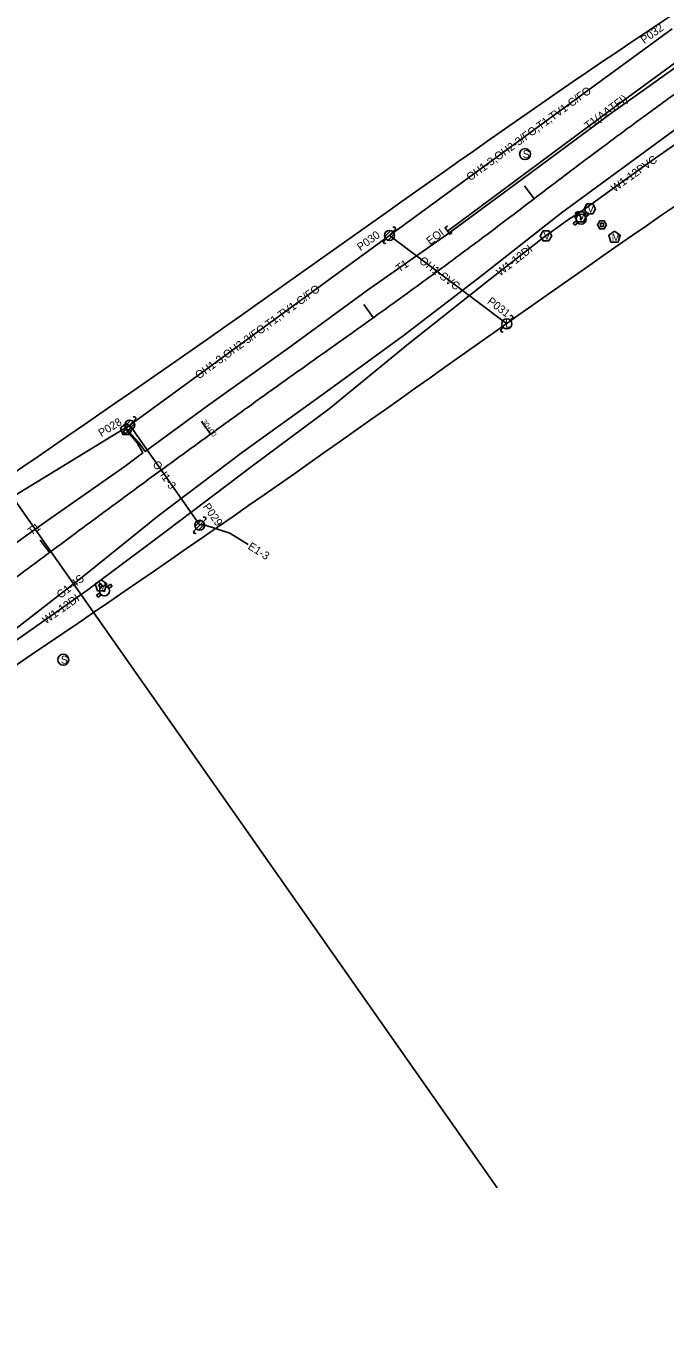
# Model space of a CAD drawing. Extents: x 1991878 to 2008544, y 770238 to 1141211.
# Drawn here: x 2005456 to 2005776, y 1139564 to 1140212 of the extents above; entities that cross this region are included whole.
import ezdxf

# ---------------------------------------------------------------- set-up
doc = ezdxf.new("R2010")
doc.units = 0
for name, color, linetype in [('RD_EX_SU_Elec', 7, 'Continuous'), ('RD_EX_SU_Gas', 7, 'Continuous'), ('RD_EX_SU_H2O', 7, 'Continuous'), ('RD_EX_SU_Ovhd', 7, 'Continuous'), ('RD_EX_SU_Pole', 7, 'Continuous'), ('RD_EX_SU_Sewer', 7, 'Continuous'), ('RD_EX_SU_SwpLmt', 7, 'Continuous'), ('RD_EX_SU_Telecom', 7, 'Continuous'), ('RD_EX_SU_TX_Elec', 7, 'Continuous'), ('RD_EX_SU_TX_Gas', 7, 'Continuous'), ('RD_EX_SU_TX_H2O', 7, 'Continuous'), ('RD_EX_SU_TX_Ovhd', 7, 'Continuous'), ('RD_EX_SU_TX_Pole', 7, 'Continuous'), ('RD_EX_SU_TX_Telecom', 7, 'Continuous'), ('RD_HC_Cl', 7, 'Continuous')]:
    doc.layers.add(name, color=color, linetype=linetype)

msp = doc.modelspace()

# ---------------------------------------------------------------- linework, layer by layer
at = {"layer": 'RD_EX_SU_Elec'}
msp.add_lwpolyline([(2005542.87, 1139962.08), (2005544.55, 1139962.45), (2005557.92, 1139958.21), (2005567.13, 1139952.46)], dxfattribs=at)
at = {"layer": 'RD_EX_SU_Gas'}
msp.add_lwpolyline([(2005803.2, 1140176.39), (2005763.13, 1140146.95), (2005723.81, 1140118.19), (2005683.92, 1140086.83), (2005644.62, 1140056.74), (2005604.18, 1140027.33), (2005564.31, 1139998.64), (2005521.91, 1139966.72), (2005504.56, 1139952.57), (2005484.04, 1139936.17), (2005443.65, 1139904.67), (2005433.24, 1139897.21), (2005404.27, 1139876.33), (2005364.62, 1139848.8), (2005341.03, 1139829.73), (2005334.6, 1139822.82), (2005321.62, 1139805.66), (2005312.49, 1139784.03), (2005307.05, 1139765.3), (2005297.89, 1139715.34), (2005290.82, 1139666.35), (2005285.78, 1139616.8), (2005285.17, 1139566.36), (2005290.52, 1139518.04)], dxfattribs=at)
at = {"layer": 'RD_EX_SU_H2O'}
for p, q in [((2005731.72, 1140118.73), (2005730.71, 1140117.98)), ((2005730.71, 1140117.98), (2005731.67, 1140116.69)), ((2005732.7, 1140117.42), (2005731.72, 1140118.73)), ((2005736.73, 1140118.3), (2005735.1, 1140117.09)), ((2005737.48, 1140117.29), (2005736.73, 1140118.3)), ((2005731.23, 1140114.21), (2005729.65, 1140113.04)), ((2005729.65, 1140113.04), (2005730.41, 1140112.03)), ((2005730.41, 1140112.03), (2005731.94, 1140113.17)), ((2005735.89, 1140116.11), (2005737.48, 1140117.29)), ((2005493.23, 1139932.93), (2005492.24, 1139932.15)), ((2005492.24, 1139932.15), (2005493.24, 1139930.89)), ((2005494.25, 1139931.65), (2005493.23, 1139932.93)), ((2005498.25, 1139932.65), (2005496.66, 1139931.39)), ((2005497.48, 1139930.43), (2005499.03, 1139931.66)), ((2005499.03, 1139931.66), (2005498.25, 1139932.65)), ((2005492.87, 1139928.4), (2005491.34, 1139927.18)), ((2005491.34, 1139927.18), (2005492.12, 1139926.19)), ((2005492.12, 1139926.19), (2005493.62, 1139927.38))]:
    msp.add_line(p, q, dxfattribs=at)
for points in [[(2005807.57, 1140171.15), (2005766.02, 1140142.13), (2005735.93, 1140120.52), (2005732.28, 1140118.09), (2005726.84, 1140114.53), (2005714.88, 1140105.91), (2005686.65, 1140083.86), (2005647.25, 1140052.78), (2005607.69, 1140020.33), (2005569.36, 1139991.81), (2005526.81, 1139959.7), (2005492.34, 1139933.84), (2005487.01, 1139929.87), (2005446.84, 1139901.54), (2005435.17, 1139892.92), (2005426.67, 1139902.32), (2005412.65, 1139920.51), (2005407.97, 1139926.34)], [(2005733.6, 1140115.07), (2005733.62, 1140115.73), (2005732.63, 1140117.39), (2005732.2, 1140118.04)]]:
    msp.add_lwpolyline(points, dxfattribs=at)
for points in [[(2005736.21, 1140116.26), (2005734.76, 1140118.76), (2005731.88, 1140118.76), (2005730.43, 1140116.26), (2005731.88, 1140113.76), (2005734.76, 1140113.76)], [(2005740.85, 1140120.22), (2005739.41, 1140122.72), (2005736.52, 1140122.72), (2005735.08, 1140120.22), (2005736.52, 1140117.72), (2005739.41, 1140117.72)], [(2005718.91, 1140106.7), (2005717.46, 1140109.2), (2005714.58, 1140109.2), (2005713.13, 1140106.7), (2005714.58, 1140104.2), (2005717.46, 1140104.2)], [(2005750.31, 1140109.11), (2005747.41, 1140107), (2005748.52, 1140103.59), (2005752.11, 1140103.59), (2005753.21, 1140107)], [(2005493.56, 1139934.88), (2005490.65, 1139932.77), (2005491.76, 1139929.36), (2005495.35, 1139929.36), (2005496.46, 1139932.77)]]:
    msp.add_lwpolyline(points, close=True, dxfattribs=at)
for centre, radius in [((2005733.6, 1140115.07), 2.52), ((2005733.6, 1140115.07), 0.315), ((2005495.21, 1139929.33), 2.52), ((2005495.21, 1139929.33), 0.315)]:
    msp.add_circle(centre, radius, dxfattribs=at)
for centre, start, end in [((2005733.6, 1140115.07), 200.01842, 228.99474), ((2005733.6, 1140115.07), 110.92525, 139.89248), ((2005733.6, 1140115.07), 24.36471, 53.34102), ((2005495.21, 1139929.33), 112.61376, 141.581), ((2005495.21, 1139929.33), 26.05322, 55.02954), ((2005495.21, 1139929.33), 201.70694, 230.68325)]:
    msp.add_arc(centre, 2.52, start, end, dxfattribs=at)
at = {"layer": 'RD_EX_SU_Ovhd'}
for p, q in [((2005637.78, 1140106.93), (2005779.22, 1140210.16)), ((2005507.86, 1140012.14), (2005637.78, 1140106.93)), ((2005637.78, 1140106.93), (2005696.44, 1140062.74)), ((2005325.23, 1139900.3), (2005507.86, 1140012.14)), ((2005542.87, 1139962.08), (2005507.86, 1140012.14))]:
    msp.add_line(p, q, dxfattribs=at)
at = {"layer": 'RD_EX_SU_Pole'}
for p, q in [((2005634.95, 1140104.1), (2005636.01, 1140105.16)), ((2005635.36, 1140106.28), (2005638.42, 1140109.35)), ((2005636.01, 1140105.16), (2005639.54, 1140108.7)), ((2005637.13, 1140104.52), (2005640.19, 1140107.58)), ((2005639.54, 1140108.7), (2005640.6, 1140109.76)), ((2005693.61, 1140059.91), (2005694.67, 1140060.97)), ((2005698.21, 1140064.51), (2005699.27, 1140065.57)), ((2005505.44, 1140011.49), (2005508.5, 1140014.55)), ((2005506.09, 1140010.37), (2005509.62, 1140013.9)), ((2005509.62, 1140013.9), (2005510.68, 1140014.96)), ((2005505.03, 1140009.31), (2005506.09, 1140010.37)), ((2005507.21, 1140009.72), (2005510.27, 1140012.78)), ((2005540.45, 1139961.43), (2005543.52, 1139964.49)), ((2005541.1, 1139960.31), (2005544.64, 1139963.84)), ((2005542.22, 1139959.66), (2005545.28, 1139962.72)), ((2005544.64, 1139963.84), (2005545.7, 1139964.9)), ((2005540.04, 1139959.25), (2005541.1, 1139960.31))]:
    msp.add_line(p, q, dxfattribs=at)
for centre in [(2005637.78, 1140106.93), (2005696.44, 1140062.74), (2005507.86, 1140012.14), (2005542.87, 1139962.08)]:
    msp.add_circle(centre, 2.5, dxfattribs=at)
for centre, start, end in [((2005640.07, 1140110.29), 315.01158, 135.01158), ((2005635.48, 1140103.57), 135.01158, 315.01158), ((2005698.74, 1140066.1), 315.01158, 135.01158), ((2005694.14, 1140059.38), 135.01158, 315.01158), ((2005510.15, 1140015.5), 315.01158, 135.01158), ((2005505.56, 1140008.78), 135.01158, 315.01158), ((2005545.17, 1139965.44), 315.01158, 135.01158), ((2005540.57, 1139958.72), 135.01158, 315.01158)]:
    msp.add_arc(centre, 0.75, start, end, dxfattribs=at)
at = {"layer": 'RD_EX_SU_Sewer'}
for points in [[(2005746.37, 1140112.21), (2005745.21, 1140114.21), (2005742.91, 1140114.21), (2005741.75, 1140112.21), (2005742.91, 1140110.21), (2005745.21, 1140110.21)], [(2005744.88, 1140113.02), (2005743.24, 1140113.02), (2005743.24, 1140111.39), (2005744.88, 1140111.39)]]:
    msp.add_lwpolyline(points, close=True, dxfattribs=at)
for centre in [(2005705.61, 1140147.54), (2005474.63, 1139894.92)]:
    msp.add_circle(centre, 2.75, dxfattribs=at)
at = {"layer": 'RD_EX_SU_SwpLmt'}
for points in [[(2005347.6, 1139821.95), (2005413.49, 1139866.73), (2005588.16, 1139984.08), (2005817.83, 1140151.69), (2006031.43, 1140278.81), (2006110.28, 1140318.03), (2006387.29, 1140416.7), (2006495.91, 1140463.06), (2006601.39, 1140518.44), (2006718.46, 1140585.62), (2006783.57, 1140627.26), (2006823.57, 1140659.06)], [(2005347.6, 1139821.95), (2005413.49, 1139866.73), (2005588.16, 1139984.08), (2005817.83, 1140151.69), (2006031.43, 1140278.81), (2006110.28, 1140318.03), (2006387.29, 1140416.7), (2006495.91, 1140463.06), (2006601.39, 1140518.44), (2006706.19, 1140578.58), (2006762.55, 1140613.92), (2006787.85, 1140632.08)], [(2005307.04, 1139891.13), (2005371.11, 1139934.66), (2005544.09, 1140050.96), (2005773.7, 1140218.52), (2005993.11, 1140349.1), (2006068.08, 1140386.39), (2006199.13, 1140434.31), (2006247.03, 1140451.84)]]:
    msp.add_open_spline(points, degree=3, dxfattribs=at)
at = {"layer": 'RD_EX_SU_Telecom'}
for points in [[(2005506.12, 1140009.88), (2005507.47, 1140009.02), (2005512.22, 1140003.56), (2005515.62, 1139999), (2005546.74, 1140021.71), (2005586.88, 1140050.43), (2005626.74, 1140079.61), (2005667.94, 1140108.45), (2005708.03, 1140137.8), (2005748.45, 1140167.76), (2005790.26, 1140197.61), (2005787.32, 1140202.47), (2005783.02, 1140209.42), (2005782.4, 1140210.68)], [(2005666.81, 1140109.05), (2005706.93, 1140138.78), (2005747.83, 1140169.15), (2005787.63, 1140198.28), (2005785.98, 1140201.22), (2005782.12, 1140209.04), (2005782.4, 1140210.68)], [(2005329.54, 1139890.24), (2005329.5, 1139888.67), (2005335.08, 1139880.48), (2005339.37, 1139876.95), (2005345.48, 1139876.61), (2005352.84, 1139881.19), (2005382.96, 1139904.56), (2005418.59, 1139928.8), (2005424.14, 1139934.13), (2005465.15, 1139963.24), (2005505.66, 1139991.65), (2005514.4, 1139998.22), (2005511.6, 1140003.28), (2005507.15, 1140008.6), (2005506.12, 1140009.88)]]:
    msp.add_lwpolyline(points, dxfattribs=at)
msp.add_lwpolyline([(2005506.12, 1140012.88), (2005503.27, 1140010.81), (2005504.36, 1140007.46), (2005507.89, 1140007.46), (2005508.98, 1140010.81)], close=True, dxfattribs=at)
at = {"layer": 'RD_EX_SU_TX_Telecom'}
msp.add_lwpolyline([(2005669.15, 1140108.44), (2005667.95, 1140107.54), (2005665.55, 1140110.73), (2005666.75, 1140111.64)], dxfattribs=at)
at = {"layer": 'RD_HC_Cl'}
for p, q in [((2005272.89, 1140227.22), (2005691.71, 1139631.08)), ((2005705.3, 1140131.64), (2005710.1, 1140125.24)), ((2005624.93, 1140072.4), (2005629.61, 1140065.91)), ((2005543.79, 1140013.91), (2005548.48, 1140007.44)), ((2005463.1, 1139954.69), (2005467.87, 1139948.27))]:
    msp.add_line(p, q, dxfattribs=at)
msp.add_open_spline([(2005275.25, 1139802.58), (2005417.33, 1139911.24), (2005548.93, 1140008.55), (2005664.1, 1140090.03), (2005747, 1140153.49), (2005819.82, 1140205.85), (2005880.88, 1140246.35), (2005986.62, 1140308.11), (2006024.68, 1140326.82), (2006100.51, 1140359.48), (2006273.91, 1140424.96), (2006364.15, 1140455.15), (2006461.52, 1140489.97), (2006524.81, 1140519.99), (2006584.45, 1140553.16), (2006699.96, 1140622.09), (2006754.11, 1140664.4), (2006830.67, 1140723.8), (2007317.85, 1141134.95)], degree=2, dxfattribs=at)

# ---------------------------------------------------------------- texts
at = {"layer": 'RD_EX_SU_H2O'}
for s, p in [('V', (2005732.11, 1140114.39)), ('V', (2005736.75, 1140118.35)), ('V', (2005714.81, 1140104.82)), ('M', (2005748.94, 1140104.07)), ('M', (2005492.19, 1139929.84))]:
    msp.add_text(s, height=3.75, dxfattribs=at).set_placement(p)
at = {"layer": 'RD_EX_SU_Pole'}
msp.add_text('L', height=4, rotation=0.01158, dxfattribs=at).set_placement((2005695.63, 1140060.81))
at = {"layer": 'RD_EX_SU_Sewer'}
for p in [(2005704.4, 1140145.57), (2005473.42, 1139892.96)]:
    msp.add_text('S', height=3.93, dxfattribs=at).set_placement(p)
at = {"layer": 'RD_EX_SU_Telecom'}
msp.add_text('T', height=3.75, dxfattribs=at).set_placement((2005504.89, 1140007.66))
at = {"layer": 'RD_EX_SU_TX_Elec'}
msp.add_text('E1-3', height=4, rotation=328.02807, dxfattribs=at).set_placement((2005566.61, 1139950.54))
at = {"layer": 'RD_EX_SU_TX_Gas'}
msp.add_text('G1-4S', height=4, rotation=37.95105, dxfattribs=at).set_placement((2005473.27, 1139925.21))
at = {"layer": 'RD_EX_SU_TX_H2O'}
for s, rotation, p in [('W1-12PVC', 35.67531, (2005750.35, 1140128.38)), ('W1-12DI', 37.99142, (2005693.12, 1140086.35)), ('W1-12DI', 35.19334, (2005465.94, 1139912.53))]:
    msp.add_text(s, height=4, rotation=rotation, dxfattribs=at).set_placement(p)
at = {"layer": 'RD_EX_SU_TX_Ovhd'}
for s, rotation, p in [('OH1-3,OH2-3/FO,T1,TV1-C/FO', 36.12425, (2005678.1, 1140133.89)), ('OH1-SVC', 323.0109, (2005652.25, 1140093.54)), ('OH1-3,OH2-3/FO,T1,TV1-C/FO', 36.11604, (2005542.42, 1140034.88)), ('OH1-3', 304.97051, (2005519.07, 1139992.61))]:
    msp.add_text(s, height=4, rotation=rotation, dxfattribs=at).set_placement(p)
at = {"layer": 'RD_EX_SU_TX_Pole'}
for s, rotation, p in [('P032', 36.12425, (2005765.19, 1140202.47)), ('P030', 36.11604, (2005623.34, 1140098.96)), ('P031', 323.0109, (2005686.33, 1140073.25)), ('P028', 31.48304, (2005493.71, 1140006.09)), ('P029', 304.97051, (2005544.25, 1139971.42))]:
    msp.add_text(s, height=4, rotation=rotation, dxfattribs=at).set_placement(p)
at = {"layer": 'RD_EX_SU_TX_Telecom'}
for s, rotation, p in [('T1(AATFI)', 36.59482, (2005737.13, 1140159.54)), ('EOI', 36.91053, (2005658.07, 1140101.97)), ('T1', 34.99382, (2005642.65, 1140088.27)), ('T1', 35.36394, (2005458.64, 1139956.74))]:
    msp.add_text(s, height=4, rotation=rotation, dxfattribs=at).set_placement(p)
at = {"layer": 'RD_HC_Cl'}
msp.add_text('30+00', height=2.5, rotation=305.95196, dxfattribs=at).set_placement((2005543.83, 1140013.86))

doc.saveas('drawing.dxf')
